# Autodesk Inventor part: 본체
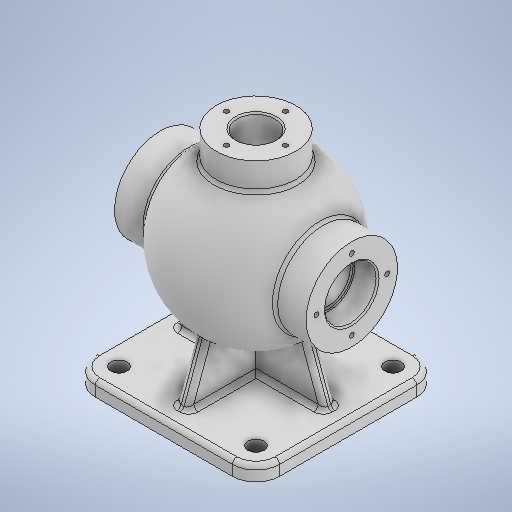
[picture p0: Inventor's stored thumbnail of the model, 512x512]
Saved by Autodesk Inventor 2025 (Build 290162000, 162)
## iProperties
Created: 2024-07
Part Number: 본체
Material: 일반
Document SubType Name: Modeling
Designer: Administrator
Density: 1 g/cm^3
Appearance: 기본값
Author: Administrator
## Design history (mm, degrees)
sketch "스케치1"
  geometry: L1 (62.5, 62.5)-(-62.5, 62.5); L2 (-62.5, 62.5)-(-62.5, -62.5); L3 (-62.5, -62.5)-(62.5, -62.5); L4 (62.5, -62.5)-(62.5, 62.5); L5 (62.5, 62.5)-(-62.5, -62.5); L6 (-62.5, 62.5)-(62.5, -62.5); 1 further point
  constraints: 12 end point, 2 midpoint, 2 parallel, 1 horizontal, 1 perpendicular
  dimensions: "d0" = 125 distance of L2.end L3.end; "d1" = 125 distance of L1.end L2.end
extrude "돌출1" new body sketch "스케치1" distance "d2" = 10; taper "d3" = 0 deg
sketch "스케치2"
  geometry: L1 (0, 62.5)-(0, -62.5) reference; L2 (139, 0)-(31, 0); A1 r 54 centre (85, 0) between (31, 0) and (139, 0); 3 further points
  constraints: 2 end point, 2 midpoint, 2 point on circle, 1 centre point, 1 horizontal, 1 horizontal alignment
  dimensions: "d5" = 54 radius of A1; "d6" = 85 distance of point (0, 0) A1.centre; "d7" = 108 distance of L2.start L2.end
revolve "회전1" sketch "스케치2" stored, may be unused: angle "d8" = 90 deg
sketch "스케치4"
  geometry: L1 (62.5, 10)-(-62.5, 10) reference; L2 (50.5, 10)-(35.236, 51.939); L3 (62.5, 0)-(62.5, 10) reference; L4 (0, 0)-(0, 46.413); L5 (-50.5, 10)-(-35.236, 51.939); L6 (-35.236, 51.939)-(35.236, 51.939); C1 r 54 at (0, 85) reference; 3 further points
  constraints: 8 end point, 2 symmetric about line, 1 horizontal, 1 point on line, 1 vertical
  dimensions: "d17" = 12 distance from line of L3 L2.start; "d18" = 20 deg angle of L3 L2
sketch "스케치3"
  geometry: L1 (129, 0)-(41, 0); C1 r 54 at (85, 0) reference; A1 r 44 centre (85, 0) between (41, 0) and (129, 0); 1 further point
  constraints: 2 end point, 2 point on circle, 1 centre point, 1 concentric, 1 horizontal
  dimensions: "d10" = 44 radius of A1; "d11" = 88 distance of L1.start L1.end
extrude "돌출2" join sketch "스케치4" stored distance "d19" = 8; taper "d20" = 0 deg
sketch "스케치5"
  geometry: L1 (10, -62.5)-(10, 62.5) reference; L2 (10, -50.5)-(58.644, -32.795); L3 (0, -62.5)-(10, -62.5) reference; L4 (0, 0)-(62.787, 0); L5 (10, 50.5)-(58.644, 32.795); L6 (58.644, 32.795)-(58.644, -32.795); 1 further point
  constraints: 8 end point, 2 symmetric about line, 1 horizontal, 1 point on line, 1 vertical
  dimensions: "d21" = 20 deg angle of L3 L2; "d22" = 12 distance from line of L3 L2.start
extrude "돌출3" join sketch "스케치5" stored distance "d23" = 8; taper "d24" = 0 deg
fillet "모깎기1" dims "d26" = 16
fillet "모깎기2" dims "d27" = 3
fillet "모깎기3" dims "d28" = 3
fillet "모깎기4" dims "d29" = 3
sketch "스케치6"
  geometry: C1 r 31 at (85, 0); A1 r 54 centre (85, 0) between (46.034, -37.385) and (46.034, 37.385) reference; 1 further point
  constraints: 1 centre point, 1 concentric
  dimensions: "d30" = 62 diameter of C1
extrude "돌출4" join sketch "스케치6" stored distance "d31" = 130; taper "d32" = 0 deg
sketch "스케치7"
  geometry: C1 r 31 at (0, 0) reference; 2 further points
  constraints: 1 coincident
hole "구멍1" sketch "스케치7" at (0, 0) diameter "d33" = 35; stored, may be unused: countersink angle "d37" = 90 deg, drill point angle "d39" = 0 deg; dims "d34" = 7.4, "d35" = 4, "d36" = 2, "d38" = 16
sketch "스케치8"
  geometry: C1 r 31 at (0, 0) reference; 2 further points
  constraints: 1 coincident
hole "구멍2" sketch "스케치8" at (0, 0) diameter "d40" = 35; stored, may be unused: countersink angle "d44" = 90 deg, drill point angle "d46" = 0 deg; dims "d41" = 6, "d42" = 4, "d43" = 2, "d45" = 16
sketch "스케치9"
  geometry: C1 r 17.5 at (0, 0) reference; 2 further points
  constraints: 1 coincident
hole "구멍3" sketch "스케치9" at (0, 0) diameter "d47" = 30; stored, may be unused: countersink angle "d51" = 90 deg, drill point angle "d53" = 0 deg; dims "d48" = 6, "d49" = 4, "d50" = 2, "d52" = 16
node "작업 평면1"
sketch "스케치10"
  geometry: C1 r 27 at (0, 0); 1 further point
  constraints: 1 centre point, 1 coincident
  dimensions: "d55" = 54 diameter of C1
extrude "돌출5" join sketch "스케치10" stored distance "d56" = 11; taper "d57" = 0 deg
revolve "회전4" stored, may be unused: angle "d58" = 90 deg
sketch "스케치11"
  geometry: A1 r 13 centre (46.5, -46.5) between (46.5, -59.5) and (59.5, -46.5) reference; 2 further points
  constraints: 1 coincident
hole "구멍4" sketch "스케치11" at (46.5, -46.5) diameter "d67" = 11; stored, may be unused: countersink angle "d71" = 90 deg, drill point angle "d73" = 0 deg; dims "d68" = 6, "d69" = 4, "d70" = 2, "d72" = 8
sketch "스케치12"
  geometry: A1 r 13 centre (46.5, 46.5) between (59.5, 46.5) and (46.5, 59.5) reference; 2 further points
  constraints: 1 coincident
hole "구멍5" sketch "스케치12" at (46.5, 46.5) diameter "d74" = 11; stored, may be unused: countersink angle "d78" = 90 deg, drill point angle "d80" = 0 deg; dims "d75" = 6, "d76" = 4, "d77" = 2, "d79" = 8
sketch "스케치13"
  geometry: A1 r 13 centre (-46.5, -46.5) between (-59.5, -46.5) and (-46.5, -59.5) reference; 2 further points
  constraints: 1 coincident
hole "구멍6" sketch "스케치13" at (-46.5, -46.5) diameter "d81" = 11; stored, may be unused: countersink angle "d85" = 90 deg, drill point angle "d87" = 0 deg; dims "d82" = 6, "d83" = 4, "d84" = 2, "d86" = 8
sketch "스케치14"
  geometry: A1 r 13 centre (-46.5, 46.5) between (-46.5, 59.5) and (-59.5, 46.5) reference; 2 further points
  constraints: 1 coincident
hole "구멍7" sketch "스케치14" at (-46.5, 46.5) diameter "d88" = 11; stored, may be unused: countersink angle "d92" = 90 deg, drill point angle "d94" = 0 deg; dims "d89" = 6, "d90" = 4, "d91" = 2, "d93" = 8
sketch "스케치15"
  geometry: C1 r 31 at (0, 0) reference; 2 further points
  constraints: 1 vertical alignment
  dimensions: "d95" = 24 distance of C1.centre point (0, 24)
hole "구멍8" sketch "스케치15" at (0, 24) diameter "d96" = 3.242; stored, may be unused: countersink angle "d100" = 90 deg, drill point angle "d102" = 120 deg; dims "d97" = 12, "d98" = 4, "d99" = 2, "d101" = 15
sketch "스케치16"
  geometry: C1 r 27 at (0, 0) reference; 2 further points
  constraints: 1 coincident
hole "구멍9" sketch "스케치16" at (0, 0) diameter "d106" = 26; stored, may be unused: countersink angle "d110" = 90 deg, drill point angle "d112" = 0 deg; dims "d107" = 12, "d108" = 4, "d109" = 2, "d111" = 40
sketch "스케치17"
  geometry: 2 further points
  constraints: 1 vertical alignment
  dimensions: "d113" = 20 distance of point (0, 0) point (0, 20)
hole "구멍10" sketch "스케치17" at (0, 20) diameter "d114" = 3.242; stored, may be unused: countersink angle "d118" = 90 deg, drill point angle "d120" = 120 deg; dims "d115" = 9, "d116" = 4, "d117" = 2, "d119" = 11
fillet "모깎기5" dims "d124" = 3
chamfer "모따기1" distance "d125" = 1; stored, may be unused: second distance "d126" = 2, angle "d127" = 45 deg
chamfer "모따기2" distance "d128" = 1; stored, may be unused: second distance "d129" = 2, angle "d130" = 45 deg
fillet "모깎기6" dims "d131" = 0.6
fillet "모깎기7" dims "d132" = 3
chamfer "모따기3" distance "d133" = 1; stored, may be unused: second distance "d134" = 2, angle "d135" = 45 deg
node "솔리드1"
pattern_circular "원형 패턴1" dims angle "d104" = 360 deg
mirror "미러1"
pattern_circular "원형 패턴2" dims angle "d122" = 360 deg
feature "A9D066F2-1C7D-4E18-AEED-F7BC21143FA4" dims "d33" = 35, "d34" = 7.4, "d35" = 4, "d36" = 2, "d37" = 90 deg, "d38" = 16, "d39" = 0
other parameters: "d13" = 0.5, "d14" = 2, "d15" = 0, "d59" = 0.5, "d60" = 2, "d61" = 0, "d63" = 0.5, "d64" = 2, "d65" = 0
